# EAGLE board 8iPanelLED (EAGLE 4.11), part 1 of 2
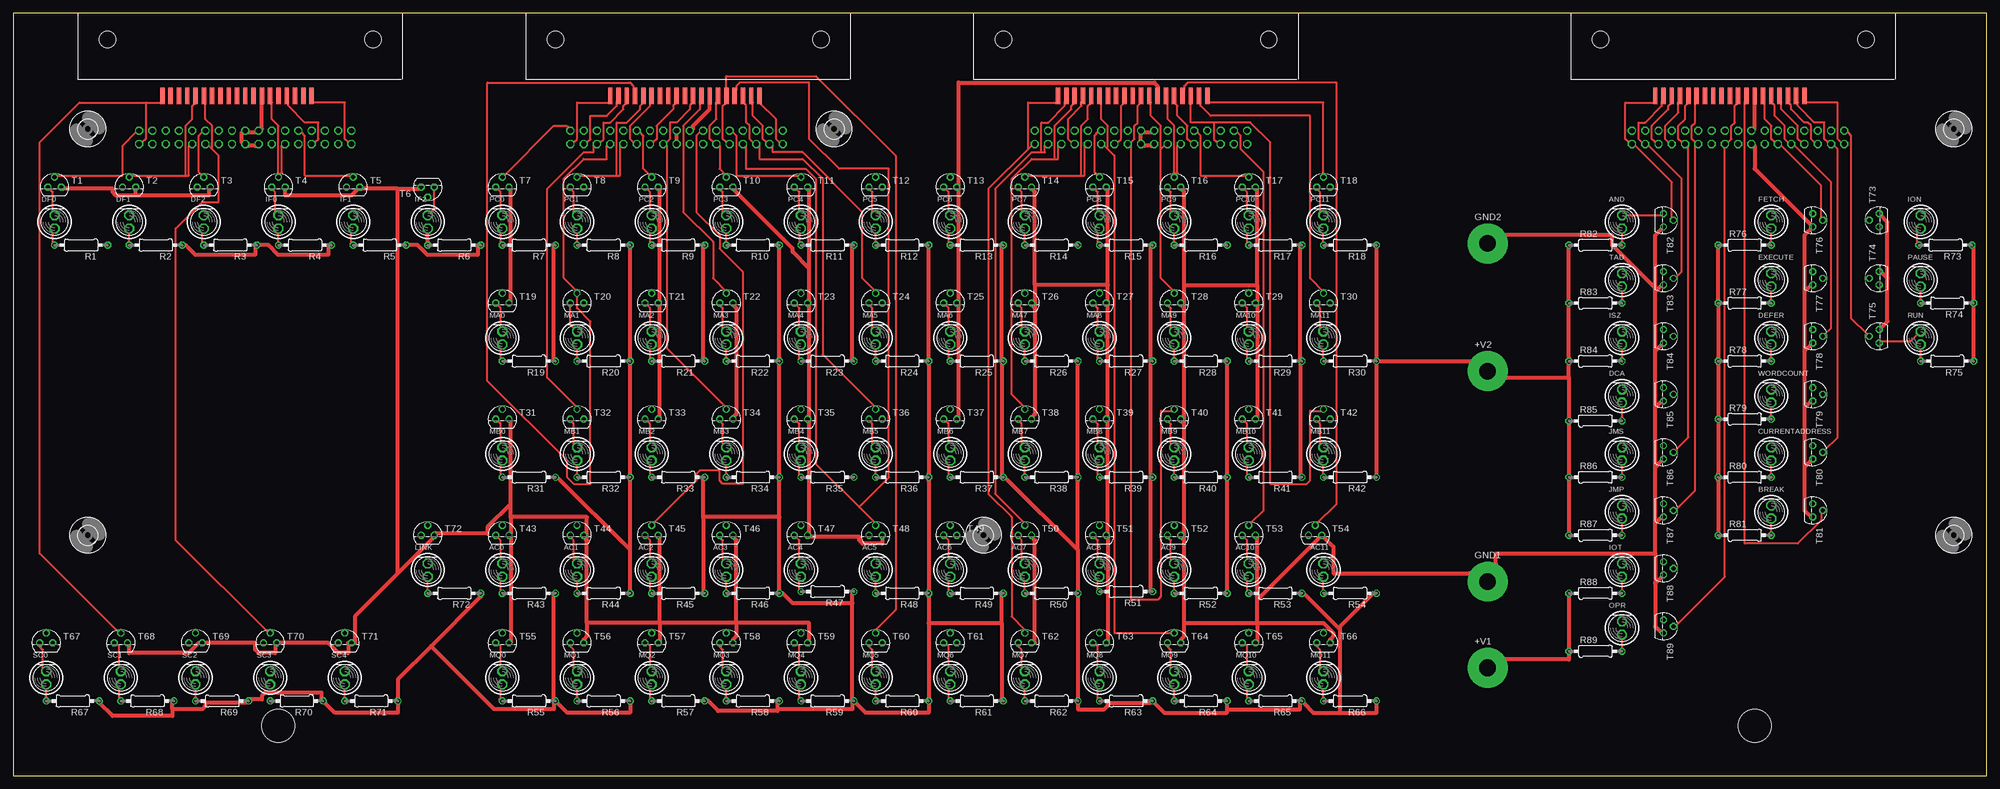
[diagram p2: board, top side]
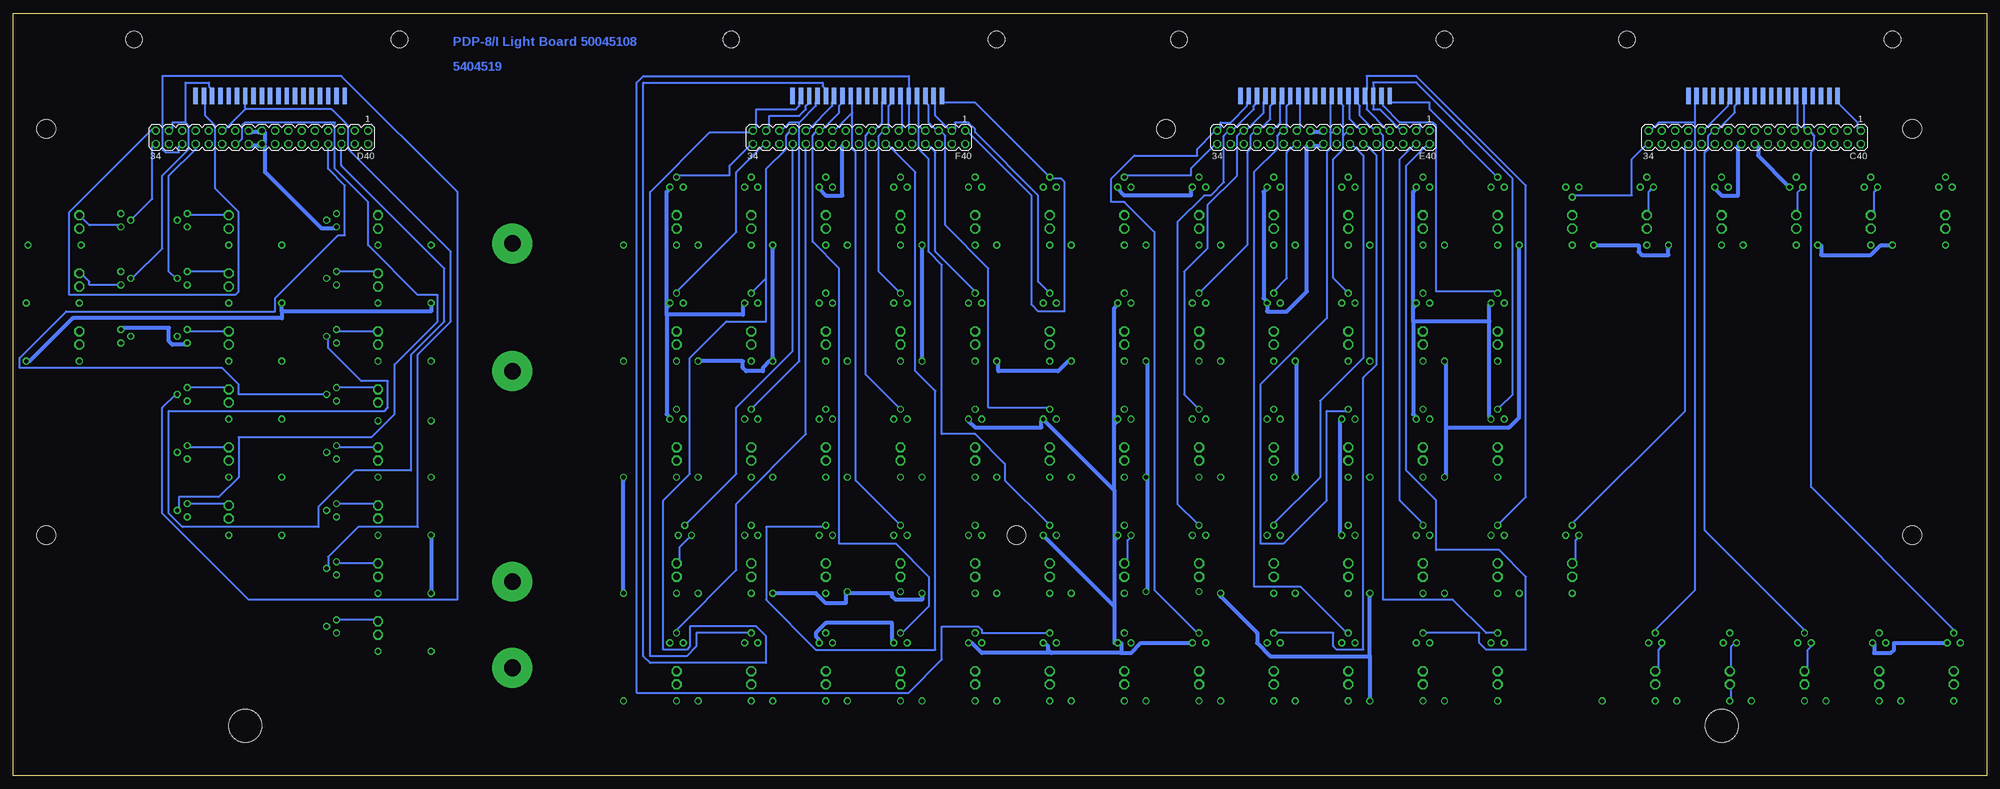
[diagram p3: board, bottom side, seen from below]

Size 377.82 x 146.05 mm. Coordinates in mm from the lower left corner, seen from the top.
Outline: 0,0 377.82,0 377.82,146.05 0,146.05 0,0
Copper layers (1*16): Top 0.035mm / dielectric 1.5mm / Bottom 0.035mm
Design rules "15mils": minimum track width 15mil, minimum drill 24mil, track to track 15mil, track to pad 10mil, pad to pad 10mil, via to via 10mil, smd to smd 10mil, copper to edge 25mil, drill to drill 10mil, minimum pad ring 10mil, minimum via ring 8mil, stop-mask expansion 0mil, vias tented up to drill 0mil, thermal gap 10mil
Net classes: 1 supply: width 0.762 mm
Holes 6.35 mm at 50.8,9.53 333.38,9.53

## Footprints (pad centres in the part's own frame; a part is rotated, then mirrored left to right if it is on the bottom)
SPADELUG = drill 3.175 pad 7.62 round: 1 0,0
BULB = drill 1.27 octagon: A 0,0; B 0,2.54
MA17-2 = drill 1.016 octagon: 1 -20.32,-1.27; 2 -20.32,1.27; 3 -17.78,-1.27; 4 -17.78,1.27; 5 -15.24,-1.27; 6 -15.24,1.27; 7 -12.7,-1.27; 8 -12.7,1.27; 9 -10.16,-1.27; 10 -10.16,1.27; 11 -7.62,-1.27; 12 -7.62,1.27; 13 -5.08,-1.27; 14 -5.08,1.27; 15 -2.54,-1.27; 16 -2.54,1.27; 17 0,-1.27; 18 0,1.27; 19 2.54,-1.27; 20 2.54,1.27; 21 5.08,-1.27; 22 5.08,1.27; 23 7.62,-1.27; 24 7.62,1.27; 25 10.16,-1.27; 26 10.16,1.27; 27 12.7,-1.27; 28 12.7,1.27; 29 15.24,-1.27; 30 15.24,1.27; 31 17.78,-1.27; 32 17.78,1.27; 33 20.32,-1.27; 34 20.32,1.27
FLEX19 = smd 3.175 x 0.838: 1 0,14.287; 2 0,12.7; 3 0,11.113; 4 0,9.525; 5 0,7.938; 6 0,6.35; 7 0,4.763; 8 0,3.175; 9 0,1.587; 10 0,0; 11 0,-1.587; 12 0,-3.175; 13 0,-4.763; 14 0,-6.35; 15 0,-7.938; 16 0,-9.525; 17 0,-11.113; 18 0,-12.7; 19 0,-14.287
0207/10 = drill 0.813 octagon: 1 -5.08,0; 2 5.08,0
TO92 = drill 0.813 octagon: 1 1.27,0; 2 0,1.905; 3 -1.27,0
STRAIN-RELIEF = hole 3.175: 7.62,56.515; 7.62,5.715
3,6 = hole 3.6: 0,0

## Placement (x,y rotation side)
+V1  LUG  [SPADELUG]  282.26,20.64 0 top
+V2  LUG  [SPADELUG]  282.26,77.47 0 top
AC0  [BULB]  93.66,38.1 0 top
AC1  [BULB]  107.95,38.1 0 top
AC2  [BULB]  122.24,38.1 0 top
AC3  [BULB]  136.53,38.1 0 top
AC4  [BULB]  150.81,38.1 0 top
AC5  [BULB]  165.1,38.1 0 top
AC6  [BULB]  179.39,38.1 0 top
AC7  [BULB]  193.68,38.1 0 top
AC8  [BULB]  207.96,38.1 0 top
AC9  [BULB]  222.25,38.1 0 top
AC10  [BULB]  236.54,38.1 0 top
AC11  [BULB]  250.82,38.1 0 top
AND  [BULB]  307.98,104.78 0 top
BREAK  [BULB]  336.55,49.21 0 top
C40  [MA17-2]  44.45,122.24 180 bottom
C40BOT  FLEX19  [FLEX19]  42.86,130.18 90 top
C40TOP  FLEX19  [FLEX19]  42.86,130.18 270 bottom
CURRENTADDRESS  [BULB]  336.55,60.33 0 top
D40  [MA17-2]  330.2,122.24 180 bottom
D40BOT  FLEX19  [FLEX19]  128.59,130.18 90 top
D40TOP  FLEX19  [FLEX19]  128.59,130.18 270 bottom
DCA  [BULB]  307.98,71.44 0 top
DEFER  [BULB]  336.55,82.55 0 top
DF0  [BULB]  7.94,104.78 0 top
DF1  [BULB]  22.23,104.78 0 top
DF2  [BULB]  36.51,104.78 0 top
E40  [MA17-2]  127,122.24 180 bottom
E40BOT  FLEX19  [FLEX19]  214.31,130.18 90 top
E40TOP  FLEX19  [FLEX19]  214.31,130.18 270 bottom
EXECUTE  [BULB]  336.55,93.66 0 top
F40  [MA17-2]  215.9,122.24 180 bottom
F40BOT  FLEX19  [FLEX19]  328.61,130.18 90 top
F40TOP  FLEX19  [FLEX19]  328.61,130.18 270 bottom
FETCH  [BULB]  336.55,104.78 0 top
GND1  LUG  [SPADELUG]  282.26,37.15 0 top
GND2  LUG  [SPADELUG]  282.26,101.92 0 top
IF0  [BULB]  50.8,104.78 0 top
IF1  [BULB]  65.09,104.78 0 top
IF2  [BULB]  79.38,104.78 0 top
ION  [BULB]  365.12,104.78 0 top
IOT  [BULB]  307.98,38.1 0 top
ISZ  [BULB]  307.98,82.55 0 top
JMP  [BULB]  307.98,49.21 0 top
JMS  [BULB]  307.98,60.33 0 top
LINK  [BULB]  79.38,38.1 0 top
MA0  [BULB]  93.66,82.55 0 top
MA1  [BULB]  107.95,82.55 0 top
MA2  [BULB]  122.24,82.55 0 top
MA3  [BULB]  136.53,82.55 0 top
MA4  [BULB]  150.81,82.55 0 top
MA5  [BULB]  165.1,82.55 0 top
MA6  [BULB]  179.39,82.55 0 top
MA7  [BULB]  193.68,82.55 0 top
MA8  [BULB]  207.96,82.55 0 top
MA9  [BULB]  222.25,82.55 0 top
MA10  [BULB]  236.54,82.55 0 top
MA11  [BULB]  250.82,82.55 0 top
MB0  [BULB]  93.66,60.33 0 top
MB1  [BULB]  107.95,60.33 0 top
MB2  [BULB]  122.24,60.33 0 top
MB3  [BULB]  136.53,60.33 0 top
MB4  [BULB]  150.81,60.33 0 top
MB5  [BULB]  165.1,60.33 0 top
MB6  [BULB]  179.39,60.33 0 top
MB7  [BULB]  193.68,60.33 0 top
MB8  [BULB]  207.96,60.33 0 top
MB9  [BULB]  222.25,60.33 0 top
MB10  [BULB]  236.54,60.33 0 top
MB11  [BULB]  250.82,60.33 0 top
MQ0  [BULB]  93.66,17.46 0 top
MQ1  [BULB]  107.95,17.46 0 top
MQ2  [BULB]  122.24,17.46 0 top
MQ3  [BULB]  136.53,17.46 0 top
MQ4  [BULB]  150.81,17.46 0 top
MQ5  [BULB]  165.1,17.46 0 top
MQ6  [BULB]  179.39,17.46 0 top
MQ7  [BULB]  193.68,17.46 0 top
MQ8  [BULB]  207.96,17.46 0 top
MQ9  [BULB]  222.25,17.46 0 top
MQ10  [BULB]  236.54,17.46 0 top
MQ11  [BULB]  250.82,17.46 0 top
OPR  [BULB]  307.98,26.99 0 top
PAUSE  [BULB]  365.12,93.66 0 top
PC0  [BULB]  93.66,104.78 0 top
PC1  [BULB]  107.95,104.78 0 top
PC2  [BULB]  122.24,104.78 0 top
PC3  [BULB]  136.53,104.78 0 top
PC4  [BULB]  150.81,104.78 0 top
PC5  [BULB]  165.1,104.78 0 top
PC6  [BULB]  179.39,104.78 0 top
PC7  [BULB]  193.68,104.78 0 top
PC8  [BULB]  207.96,104.78 0 top
PC9  [BULB]  222.25,104.78 0 top
PC10  [BULB]  236.54,104.78 0 top
PC11  [BULB]  250.82,104.78 0 top
R1  1.5K  [0207/10]  13.02,101.6 180 top
R2  1.5K  [0207/10]  27.3,101.6 180 top
R3  1.5K  [0207/10]  41.59,101.6 180 top
R4  1.5K  [0207/10]  55.88,101.6 180 top
R5  1.5K  [0207/10]  70.17,101.6 180 top
R6  1.5K  [0207/10]  84.45,101.6 180 top
R7  1.5K  [0207/10]  98.74,101.6 180 top
R8  1.5K  [0207/10]  113.03,101.6 180 top
R9  1.5K  [0207/10]  127.32,101.6 180 top
R10  1.5K  [0207/10]  141.6,101.6 180 top
R11  1.5K  [0207/10]  155.89,101.6 180 top
R12  1.5K  [0207/10]  170.18,101.6 180 top
R13  1.5K  [0207/10]  184.47,101.6 180 top
R14  1.5K  [0207/10]  198.75,101.6 180 top
R15  1.5K  [0207/10]  213.04,101.6 180 top
R16  1.5K  [0207/10]  227.33,101.6 180 top
R17  1.5K  [0207/10]  241.62,101.6 180 top
R18  1.5K  [0207/10]  255.91,101.6 180 top
R19  1.5K  [0207/10]  98.74,79.38 180 top
R20  1.5K  [0207/10]  113.03,79.38 180 top
R21  1.5K  [0207/10]  127.32,79.38 180 top
R22  1.5K  [0207/10]  141.6,79.38 180 top
R23  1.5K  [0207/10]  155.89,79.38 180 top
R24  1.5K  [0207/10]  170.18,79.38 180 top
R25  1.5K  [0207/10]  184.47,79.38 180 top
R26  1.5K  [0207/10]  198.75,79.38 180 top
R27  1.5K  [0207/10]  213.04,79.38 180 top
R28  1.5K  [0207/10]  227.33,79.38 180 top
R29  1.5K  [0207/10]  241.62,79.38 180 top
R30  1.5K  [0207/10]  255.91,79.38 180 top
R31  1.5K  [0207/10]  98.74,57.15 180 top
R32  1.5K  [0207/10]  113.03,57.15 180 top
R33  1.5K  [0207/10]  127.32,57.15 180 top
R34  1.5K  [0207/10]  141.6,57.15 180 top
R35  1.5K  [0207/10]  155.89,57.15 180 top
R36  1.5K  [0207/10]  170.18,57.15 180 top
R37  1.5K  [0207/10]  184.47,57.15 180 top
R38  1.5K  [0207/10]  198.75,57.15 180 top
R39  1.5K  [0207/10]  213.04,57.15 180 top
R40  1.5K  [0207/10]  227.33,57.15 180 top
R41  1.5K  [0207/10]  241.62,57.15 180 top
R42  1.5K  [0207/10]  255.91,57.15 180 top
R43  1.5K  [0207/10]  98.74,34.92 180 top
R44  1.5K  [0207/10]  113.03,34.92 180 top
R45  1.5K  [0207/10]  127.32,34.92 180 top
R46  1.5K  [0207/10]  141.6,34.92 180 top
R47  1.5K  [0207/10]  155.89,35.24 180 top
R48  1.5K  [0207/10]  170.18,34.92 180 top
R49  1.5K  [0207/10]  184.47,34.92 180 top
R50  1.5K  [0207/10]  198.75,34.92 180 top
R51  1.5K  [0207/10]  213.04,35.24 180 top
R52  1.5K  [0207/10]  227.33,34.92 180 top
R53  1.5K  [0207/10]  241.62,34.92 180 top
R54  1.5K  [0207/10]  255.91,34.92 180 top
R55  1.5K  [0207/10]  98.74,14.29 180 top
R56  1.5K  [0207/10]  113.03,14.29 180 top
R57  1.5K  [0207/10]  127.32,14.29 180 top
R58  1.5K  [0207/10]  141.6,14.29 180 top
R59  1.5K  [0207/10]  155.89,14.29 180 top
R60  1.5K  [0207/10]  170.18,14.29 180 top
R61  1.5K  [0207/10]  184.47,14.29 180 top
R62  1.5K  [0207/10]  198.75,14.29 180 top
R63  1.5K  [0207/10]  213.04,14.29 180 top
R64  1.5K  [0207/10]  227.33,14.29 180 top
R65  1.5K  [0207/10]  241.62,14.29 180 top
R66  1.5K  [0207/10]  255.91,14.29 180 top
R67  1.5K  [0207/10]  11.43,14.29 180 top
R68  1.5K  [0207/10]  25.72,14.29 180 top
R69  1.5K  [0207/10]  40.01,14.29 180 top
R70  1.5K  [0207/10]  54.29,14.29 180 top
R71  1.5K  [0207/10]  68.58,14.29 180 top
R72  1.5K  [0207/10]  84.45,34.92 180 top
R73  1.5K  [0207/10]  369.89,101.6 180 top
R74  1.5K  [0207/10]  370.2,90.49 180 top
R75  1.5K  [0207/10]  370.2,79.38 180 top
R76  1.5K  [0207/10]  331.47,101.6 0 top
R77  1.5K  [0207/10]  331.47,90.49 0 top
R78  1.5K  [0207/10]  331.47,79.38 0 top
R79  1.5K  [0207/10]  331.47,68.26 0 top
R80  1.5K  [0207/10]  331.47,57.15 0 top
R81  1.5K  [0207/10]  331.47,46.04 0 top
R82  1.5K  [0207/10]  302.89,101.6 0 top
R83  1.5K  [0207/10]  302.89,90.49 0 top
R84  1.5K  [0207/10]  302.89,79.38 0 top
R85  1.5K  [0207/10]  302.89,67.94 0 top
R86  1.5K  [0207/10]  302.89,57.15 0 top
R87  1.5K  [0207/10]  302.89,46.04 0 top
R88  1.5K  [0207/10]  302.89,34.92 0 top
R89  1.5K  [0207/10]  302.89,23.81 0 top
RUN  [BULB]  365.12,82.55 0 top
SC0  [BULB]  6.35,17.46 0 top
SC1  [BULB]  20.64,17.46 0 top
SC2  [BULB]  34.92,17.46 0 top
SC3  [BULB]  49.21,17.46 0 top
SC4  [BULB]  63.5,17.46 0 top
T1  2N2222  [TO92]  7.94,112.71 0 top
T2  2N2222  [TO92]  22.23,112.71 0 top
T3  2N2222  [TO92]  36.51,112.71 0 top
T4  2N2222  [TO92]  50.8,112.71 0 top
T5  2N2222  [TO92]  65.09,112.71 0 top
T6  2N2222  [TO92]  79.38,112.71 180 top
T7  2N2222  [TO92]  93.66,112.71 0 top
T8  2N2222  [TO92]  107.95,112.71 0 top
T9  2N2222  [TO92]  122.24,112.71 0 top
T10  2N2222  [TO92]  136.53,112.71 0 top
T11  2N2222  [TO92]  150.81,112.71 0 top
T12  2N2222  [TO92]  165.1,112.71 0 top
T13  2N2222  [TO92]  179.39,112.71 0 top
T14  2N2222  [TO92]  193.68,112.71 0 top
T15  2N2222  [TO92]  207.96,112.71 0 top
T16  2N2222  [TO92]  222.25,112.71 0 top
T17  2N2222  [TO92]  236.54,112.71 0 top
T18  2N2222  [TO92]  250.82,112.71 0 top
T19  2N2222  [TO92]  93.66,90.49 0 top
T20  2N2222  [TO92]  107.95,90.49 0 top
T21  2N2222  [TO92]  122.24,90.49 0 top
T22  2N2222  [TO92]  136.53,90.49 0 top
T23  2N2222  [TO92]  150.81,90.49 0 top
T24  2N2222  [TO92]  165.1,90.49 0 top
T25  2N2222  [TO92]  179.39,90.49 0 top
T26  2N2222  [TO92]  193.68,90.49 0 top
T27  2N2222  [TO92]  207.96,90.49 0 top
T28  2N2222  [TO92]  222.25,90.49 0 top
T29  2N2222  [TO92]  236.54,90.49 0 top
T30  2N2222  [TO92]  250.82,90.49 0 top
T31  2N2222  [TO92]  93.66,68.26 0 top
T32  2N2222  [TO92]  107.95,68.26 0 top
T33  2N2222  [TO92]  122.24,68.26 0 top
T34  2N2222  [TO92]  136.53,68.26 0 top
T35  2N2222  [TO92]  150.81,68.26 0 top
T36  2N2222  [TO92]  165.1,68.26 0 top
T37  2N2222  [TO92]  179.39,68.26 0 top
T38  2N2222  [TO92]  193.68,68.26 0 top
T39  2N2222  [TO92]  207.96,68.26 0 top
T40  2N2222  [TO92]  222.25,68.26 0 top
T41  2N2222  [TO92]  236.54,68.26 0 top
T42  2N2222  [TO92]  250.82,68.26 0 top
T43  2N2222  [TO92]  93.66,46.04 0 top
T44  2N2222  [TO92]  107.95,46.04 0 top
T45  2N2222  [TO92]  122.24,46.04 0 top
T46  2N2222  [TO92]  136.53,46.04 0 top
T47  2N2222  [TO92]  150.81,46.04 0 top
T48  2N2222  [TO92]  165.1,46.04 0 top
T49  2N2222  [TO92]  179.39,46.04 0 top
T50  2N2222  [TO92]  193.68,46.04 0 top
T51  2N2222  [TO92]  207.96,46.04 0 top
T52  2N2222  [TO92]  222.25,46.04 0 top
T53  2N2222  [TO92]  236.54,46.04 0 top
T54  2N2222  [TO92]  249.24,46.04 0 top
T55  2N2222  [TO92]  93.66,25.4 0 top
T56  2N2222  [TO92]  107.95,25.4 0 top
T57  2N2222  [TO92]  122.24,25.4 0 top
T58  2N2222  [TO92]  136.53,25.4 0 top
T59  2N2222  [TO92]  150.81,25.4 0 top
T60  2N2222  [TO92]  165.1,25.4 0 top
T61  2N2222  [TO92]  179.39,25.4 0 top
T62  2N2222  [TO92]  193.68,25.4 0 top
T63  2N2222  [TO92]  207.96,25.4 0 top
T64  2N2222  [TO92]  222.25,25.4 0 top
T65  2N2222  [TO92]  236.54,25.4 0 top
T66  2N2222  [TO92]  250.82,25.4 0 top
T67  2N2222  [TO92]  6.35,25.4 0 top
T68  2N2222  [TO92]  20.64,25.4 0 top
T69  2N2222  [TO92]  34.92,25.4 0 top
T70  2N2222  [TO92]  49.21,25.4 0 top
T71  2N2222  [TO92]  63.5,25.4 0 top
T72  2N2222  [TO92]  79.38,46.04 0 top
T73  2N2222  [TO92]  357.19,106.36 90 top
T74  2N2222  [TO92]  357.19,95.25 90 top
T75  2N2222  [TO92]  357.19,84.14 90 top
T76  2N2222  [TO92]  344.49,106.36 270 top
T77  2N2222  [TO92]  344.49,95.25 270 top
T78  2N2222  [TO92]  344.49,84.14 270 top
T79  2N2222  [TO92]  344.49,73.03 270 top
T80  2N2222  [TO92]  344.49,61.91 270 top
T81  2N2222  [TO92]  344.49,50.8 270 top
T82  2N2222  [TO92]  315.91,106.36 270 top
T83  2N2222  [TO92]  315.91,95.25 270 top
T84  2N2222  [TO92]  315.91,84.14 270 top
T85  2N2222  [TO92]  315.91,73.03 270 top
T86  2N2222  [TO92]  315.91,61.91 270 top
T87  2N2222  [TO92]  315.91,50.8 270 top
T88  2N2222  [TO92]  315.91,39.69 270 top
T89  2N2222  [TO92]  315.91,28.57 270 top
TAD  [BULB]  307.98,93.66 0 top
U$1  [STRAIN-RELIEF]  74.61,133.35 90 top
U$2  [STRAIN-RELIEF]  160.34,133.35 90 top
U$3  [STRAIN-RELIEF]  246.06,133.35 90 top
U$4  [STRAIN-RELIEF]  360.36,133.35 90 top
U$5  [3,6]  371.48,123.83 0 top
U$6  [3,6]  371.48,46.04 0 top
U$7  [3,6]  185.74,46.04 0 top
U$8  [3,6]  14.29,46.04 0 top
U$9  [3,6]  14.29,123.83 0 top
U$11  [3,6]  157.16,123.83 0 top
WORDCOUNT  [BULB]  336.55,71.44 0 top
